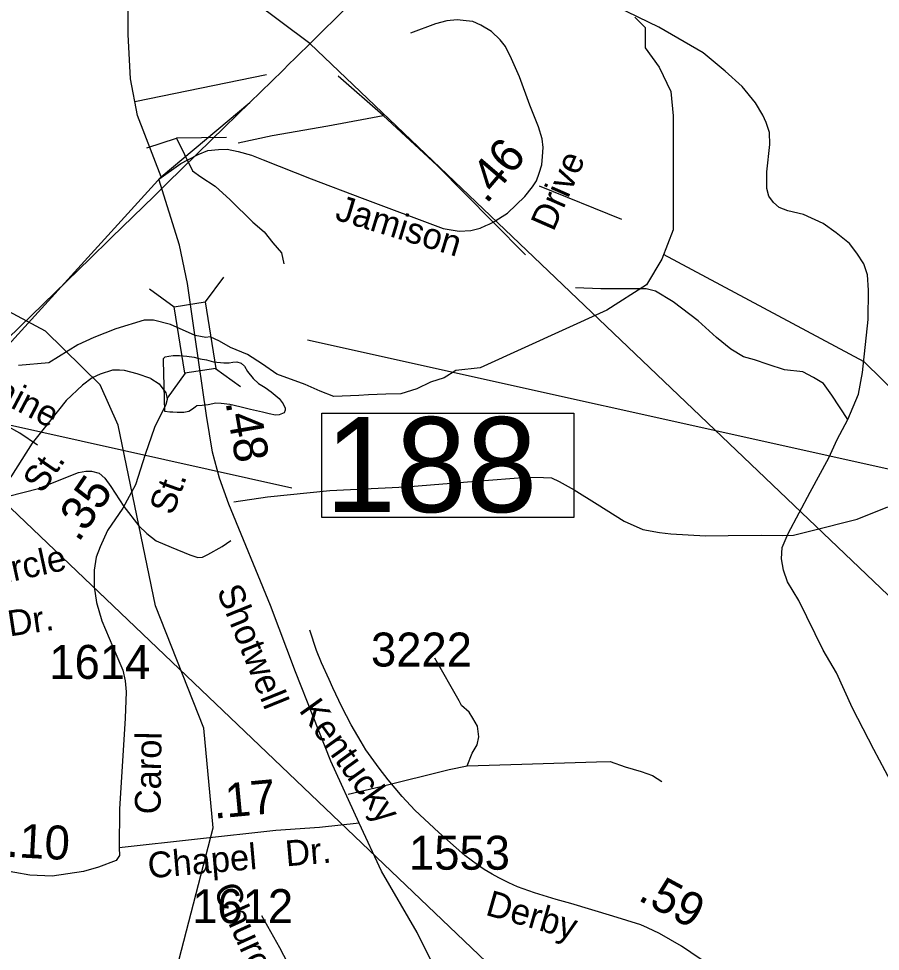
# Model space of a CAD drawing. Extents: x 2169602 to 2449496, y 721995 to 810662.
# Drawn here: x 2397017 to 2400191, y 770629 to 774064 of the extents above; entities that cross this region are included whole.
import ezdxf

# ---------------------------------------------------------------- set-up
doc = ezdxf.new("R2010")
doc.units = 0
doc.layers.add('Default', color=7, linetype='Continuous')

msp = doc.modelspace()

# ---------------------------------------------------------------- linework, layer by layer
at = {"layer": 'Default'}
for p, q in [((2397929.8, 773856.9), (2397444.7, 773758.4)), ((2398359.1, 773708), (2398194.2, 773852.1)), ((2397488.4, 773587.9), (2397598.6, 773623.5)), ((2397782.5, 773626.3), (2397598.6, 773623.5)), ((2397598.6, 773623.5), (2397657.5, 773503.9)), ((2398934, 773448.1), (2399237.7, 773326.2)), ((2398764.9, 773314.7), (2398884.4, 773194.6)), ((2397770.8, 773112.6), (2397704.2, 773021)), ((2397498.3, 773069.4), (2397589.9, 773002.9)), ((2395064.8, 772994), (2398022.8, 772336.6)), ((2398080.6, 772881.1), (2401038.6, 772223.8)), ((2397742.5, 772776.1), (2397834.1, 772709.6)), ((2397630.7, 772758.4), (2397564.2, 772666.8))]:
    msp.add_line(p, q, dxfattribs=at)
for points in [[(2389396, 765530.5), (2389873.7, 765993.4), (2389932.2, 766050), (2389976.3, 766092.7), (2391349.7, 767422.8), (2391498.4, 767552.8), (2391855.4, 767888.1), (2392186.8, 768223.2), (2394046.1, 769967.9), (2396780.6, 772645.2), (2397542.2, 773482.1), (2397868.3, 773755.4), (2397989.5, 773873.8), (2398013.9, 773897.7), (2398034.4, 773917.9), (2398098.8, 773981.2), (2398223.7, 774104.3), (2398525.7, 774401.5), (2398527.8, 774403.5), (2398862.2, 774727.1), (2399383.8, 775209.8), (2399485.8, 775316.7)], [(2398089.9, 773972.5), (2397778.5, 774206.3), (2397521.3, 774474.8)], [(2397542.2, 773482.1), (2397454.6, 773707.2), (2397428.5, 773842.2), (2397420.6, 774005.6), (2397420.6, 774129.1), (2397425.9, 774209.8), (2397445.2, 774303)], [(2400071.9, 772588.2), (2400110.4, 772680.5), (2400125.8, 772760.9), (2400146.3, 772955.9), (2400147.2, 773063.7), (2400143.7, 773120.1), (2400130, 773161.2), (2400104.4, 773200.5), (2400077.9, 773236.5), (2400028.3, 773275.8), (2399980.4, 773310), (2399908.5, 773342.5), (2399850.4, 773356.2), (2399817.9, 773368.2), (2399797.4, 773387), (2399780.3, 773410.9), (2399773.4, 773438.3), (2399773.4, 773499.9), (2399784.5, 773600.8), (2399782.8, 773645.3), (2399770.8, 773681.2), (2399758.9, 773708.6), (2399731.5, 773754.7), (2399681.9, 773814.6), (2399619.5, 773871), (2399539.1, 773937.8), (2399374.9, 774033.5), (2399103.8, 774165.3)], [(2392186.8, 768223.2), (2394046.1, 769967.9), (2396780.6, 772645.2), (2397542.2, 773482.1), (2397868.3, 773755.4), (2397989.5, 773873.8), (2398013.9, 773897.7), (2398034.4, 773917.9), (2398098.8, 773981.2), (2398223.7, 774104.3)], [(2410998.9, 759007.9), (2409859, 760053.1), (2407211.5, 762601.4), (2405778.5, 763946.8), (2405684, 764042.1), (2405083.2, 764574.5), (2404665, 764982.2), (2402074.2, 767418.4), (2399573.8, 769793.5), (2395074.1, 774085.3)], [(2396844.7, 772758.7), (2397281, 773182), (2397351.2, 773250.5), (2397359, 773258.1), (2397515.4, 773410.9), (2397538.8, 773433.8), (2397562.2, 773456.7), (2397563.4, 773457.8), (2397727.6, 773618.2), (2397868.3, 773755.4), (2397989.5, 773873.8), (2398013.9, 773897.8), (2398034.4, 773918), (2398098.8, 773981.2), (2398223.7, 774104.3)], [(2399287.2, 774069.4), (2399324.9, 774031.7), (2399324.9, 773956.3), (2399376.7, 773885.6), (2399419.1, 773796), (2399428.5, 773706.4), (2399428.5, 773451.9), (2399428.5, 773286.9), (2399386.1, 773178.5), (2399329.6, 773084.2), (2399183.6, 772989.9), (2398717.2, 772777.8), (2398627.7, 772768.4), (2398584.3, 772741.1), (2398534.3, 772725.6), (2398483.5, 772700.6), (2398424.9, 772682.5), (2398369.7, 772681.6), (2398305.1, 772678.2), (2398269.7, 772675.6), (2398178, 772672.9), (2398128.1, 772691.5), (2398072.5, 772717.1), (2397968.3, 772754.2), (2397915.3, 772791.5), (2397859.2, 772827.6), (2397796.9, 772852.5), (2397757.1, 772876.2), (2397722.2, 772892.4), (2397706, 772889.9), (2397667.2, 772897.4), (2397576, 772938), (2397514, 772953.3), (2397479.1, 772953.4), (2397374.5, 772921.4), (2397293.1, 772889.4), (2397234.9, 772863.2), (2397127.4, 772796.3), (2397016.6, 772787.2)], [(2397533.5, 773472.5), (2397614.8, 773530.6), (2397640, 773543.7), (2397678, 773564.2), (2397713.4, 773578.2), (2397753.4, 773581.7), (2397784.5, 773582.9), (2397825, 773574.8), (2397874.8, 773561.1), (2397917.7, 773544.3), (2398094.3, 773474.6), (2398282.6, 773403), (2398580.9, 773291.5), (2398640, 773281.5), (2398682.4, 773283.4), (2398716.6, 773292.1), (2398737.9, 773302.8), (2398749.6, 773307.4), (2398764.9, 773314.7), (2398817.9, 773347.3), (2398881, 773408.6), (2398910.3, 773444.7), (2398924, 773467.1), (2398933.9, 773494.5), (2398944.5, 773525.6), (2398947, 773556.1), (2398948.9, 773589.1), (2398945.8, 773621.5), (2398932.1, 773665.7), (2398900, 773746.1), (2398861.4, 773849.4), (2398832.4, 773916), (2398810.7, 773962.1), (2398790.1, 773986.4), (2398759, 774017.5), (2398719.7, 774040), (2398690.5, 774053.7), (2398665, 774056.8), (2398631.9, 774060.5), (2398594.3, 774056.8), (2398551.9, 774045.6), (2398459.8, 774011.3)], [(2414014.7, 758895), (2412874.9, 759940.3), (2410227.4, 762488.5), (2408794.3, 763834), (2408699.9, 763929.3), (2408099, 764461.7), (2407680.9, 764869.3), (2405090.1, 767305.6), (2402589.6, 769680.7), (2398089.9, 773972.5)], [(2397825.5, 773606.6), (2397951, 773634.2), (2398155.4, 773669.6), (2398300.9, 773696.2), (2398359.1, 773708)], [(2398359.1, 773708), (2398558.7, 773523.7), (2398764.9, 773314.7)], [(2397657.5, 773503.9), (2397687.9, 773481.7), (2397740.2, 773447.8), (2397796.4, 773396.3), (2397878.9, 773314.8), (2397920.9, 773279), (2397953.3, 773239.1), (2397985.5, 773201.5), (2397993.7, 773161.5)], [(2397666.2, 772899.8), (2397638.8, 773089.1), (2397608.9, 773229.9), (2397533.5, 773472.5)], [(2398080.6, 767097), (2398111.6, 767572), (2398093.6, 767736.3), (2398174.8, 768180.8), (2398115.7, 768313.2), (2397956.6, 768460.8), (2397578.7, 768983.5), (2397502.6, 769142.5), (2397468.8, 769307.2), (2397483.8, 769592.3), (2397524.8, 769768.7), (2397562.7, 770424), (2397733.8, 771083.1), (2397698.7, 771451.2), (2397520.7, 771900.9), (2397383.8, 772566.4), (2397316.9, 772715.3), (2397115.8, 772913), (2396376.9, 773308.2)], [(2401096.5, 766984.1), (2401127.4, 767459.1), (2401109.4, 767623.5), (2401190.6, 768068), (2401131.6, 768200.3), (2400972.4, 768348), (2400594.5, 768870.7), (2400518.5, 769029.7), (2400484.6, 769194.4), (2400499.6, 769479.5), (2400540.6, 769655.8), (2400578.6, 770311.1), (2400749.6, 770970.3), (2400714.5, 771338.4), (2400536.5, 771788.1), (2400399.6, 772453.5), (2400332.7, 772602.5), (2400131.6, 772800.1), (2399392.8, 773195.4)], [(2400071.9, 772588.2), (2400012, 772677.1), (2399981.2, 772719.9), (2399945.3, 772742.1), (2399906, 772762.7), (2399837.6, 772771.2), (2399777.7, 772790), (2399728.1, 772807.1), (2399687, 772819.1), (2399640.8, 772846.5), (2399587.8, 772889.2), (2399520.3, 772950.8), (2399427.9, 773020.9), (2399362.9, 773060.3), (2399328.7, 773068.8), (2399285.9, 773068.8), (2399161.1, 773068.8), (2399068.7, 773072.2)], [(2398271.4, 771100.3), (2398166.2, 771329.5), (2398036.7, 771658.2), (2397944.5, 771902.3), (2397791.3, 772275.9), (2397756.5, 772371.8), (2397730.3, 772467.7), (2397708.5, 772602.2), (2397666.2, 772899.8)], [(2397555.2, 772617), (2397550.5, 772805.1), (2397550.5, 772812.8), (2397556.2, 772818.9), (2397570.2, 772821.2), (2397585.7, 772823.3), (2397609.9, 772823.3), (2397636, 772821.4), (2397663.9, 772817.6), (2397685.8, 772811.8), (2397708.6, 772807.9), (2397734, 772800), (2397772.5, 772796.2), (2397792, 772796.1), (2397806, 772798.5), (2397820.3, 772800.4), (2397836.5, 772794.7), (2397848.4, 772784.8), (2397860.3, 772764.7), (2397880.6, 772738.9), (2397900.7, 772720.9), (2397924.7, 772705.1), (2397946.8, 772689.2), (2397976.8, 772665.6), (2397990.9, 772645.6), (2397998.9, 772629.4), (2397998.9, 772621.7), (2397995, 772611.7), (2397977, 772605.5), (2397963, 772603.5), (2397939.5, 772609.2), (2397915.3, 772614.9), (2397871, 772624.8), (2397831, 772634.5), (2397794.9, 772642.4), (2397763.3, 772646.4), (2397743.2, 772648.2), (2397714.9, 772641.9), (2397693, 772639.9), (2397673.1, 772637.7), (2397667.1, 772633.7), (2397657.3, 772625.4), (2397643.4, 772617.4), (2397625.1, 772613.3), (2397601.3, 772613.2), (2397585.1, 772615.3), (2397573.2, 772615.1), (2397555.2, 772617)], [(2397503.7, 772738.3), (2397453.4, 772755.6), (2397406.5, 772768.2), (2397388.3, 772769.7), (2397362.8, 772769.4), (2397317.4, 772754.7), (2397288.1, 772741.1), (2397252, 772713.7), (2397192.2, 772657.6), (2397129.9, 772580.4), (2397067, 772500.1), (2396990.8, 772380.5), (2396931.6, 772300.8), (2396899.2, 772235.4), (2396876.8, 772172.6), (2396851.3, 772083.5), (2396796.2, 771892.4), (2396664.2, 771359.3), (2396601.3, 771118.4), (2396594.4, 771049.9), (2396600, 771032.4), (2396621.8, 771015.6), (2396671, 771000.1), (2396894.1, 770944.8)], [(2397503.7, 772738.3), (2397534.3, 772718.6), (2397558.6, 772686.3), (2397561.1, 772675.7), (2397564.2, 772662), (2397559.3, 772643.3), (2397516.7, 772558.6), (2397483.1, 772458.4), (2397446.7, 772346.9), (2397400.6, 772261), (2397344.6, 772178.8), (2397317.5, 772118.4), (2397302.5, 772081), (2397294.5, 772032.5), (2397294.5, 771971.4), (2397303.8, 771913.5), (2397323.4, 771846.3), (2397363.3, 771750.4), (2397400.6, 771664.5), (2397409.3, 771624.6), (2397412.4, 771584.1), (2397409.3, 771487), (2397388.8, 771152.6), (2397386.9, 771010)], [(2397086.5, 772493.1), (2397021.3, 772536.8), (2396913.9, 772596.5), (2396862.2, 772627), (2396830.4, 772638.9), (2396807.7, 772644.9), (2396780.6, 772645.2)], [(2400504.6, 770797.3), (2400447.3, 770898.2), (2400363.5, 771031.6), (2400230.1, 771254), (2400167.7, 771372), (2400089, 771524.3), (2400030, 771654.3), (2399980.4, 771738.1), (2399891.4, 771921.1), (2399849.5, 771989.5), (2399834.1, 772032.3), (2399827.3, 772075), (2399829, 772116.1), (2399851.2, 772167.4), (2399932.5, 772319.6), (2400000.9, 772446.2), (2400031.7, 772514.6), (2400071.9, 772588.2)], [(2396919.8, 772290.4), (2397090.1, 772334), (2397202.6, 772378.8), (2397237.6, 772393), (2397263.8, 772397.4), (2397285.6, 772397.4), (2397312.9, 772389.7), (2397333.7, 772371.2), (2397356.6, 772340.6), (2397404.7, 772267.4), (2397459.3, 772195.9), (2397488.7, 772167.5), (2397523.7, 772141.3), (2397578.3, 772117.3), (2397647.1, 772088.9), (2397676.6, 772079.1), (2397694, 772080.2), (2397713.7, 772090), (2397766.1, 772119.5), (2397798.9, 772141.9)], [(2397809.5, 772284), (2397932.9, 772302.6), (2398163.3, 772326.6), (2398442.8, 772339.2), (2398701.6, 772360.4), (2398888.4, 772375.7), (2398950.6, 772374.1), (2398980.1, 772373), (2399008.5, 772359.9), (2399063.1, 772328.2), (2399148.3, 772275.8), (2399247.6, 772213), (2399316.4, 772182.4), (2399377.6, 772171.5), (2399419.1, 772166.1), (2399546.9, 772159), (2399630.9, 772160.1), (2399754.3, 772161.2), (2399829.7, 772160.1), (2399871.2, 772162.2), (2399935.6, 772177.5), (2400106, 772221.2), (2400218.5, 772266)], [(2399565.9, 770574.9), (2399458.1, 770647.3), (2399377.9, 770694.7), (2399333.5, 770715.7), (2399308.3, 770726.1), (2399205.3, 770758.4), (2399050.5, 770805.1), (2398996.4, 770819.4), (2398917.6, 770843.7), (2398854.1, 770866.8), (2398822, 770881.6), (2398786.3, 770899.6), (2398760.7, 770912.7), (2398731.6, 770930.4), (2398706.6, 770947.4), (2398660.2, 770981.6), (2398565.2, 771066), (2398475.8, 771149.1), (2398429, 771198.8), (2398378, 771260.9), (2398344.4, 771302.9), (2398295.2, 771370.6), (2398278.3, 771400.4), (2398242.3, 771462.5), (2398207.7, 771528.8), (2398174.6, 771599.4), (2398160.2, 771629.9), (2398132.6, 771691.7), (2398114.2, 771737.4), (2398089.5, 771811.4)], [(2398669.2, 771311.5), (2398687.4, 771358.5), (2398706, 771389.1), (2398712.6, 771418.6), (2398707.1, 771457.9), (2398689.6, 771487.4), (2398676.5, 771510.3), (2398648.1, 771534.3), (2398639.4, 771551.8), (2398549.8, 771709.1)], [(2398669.2, 771311.5), (2398870.9, 771318.7), (2399146.1, 771326.3), (2399196.3, 771328.5), (2399250.9, 771308.8), (2399309.9, 771291.4), (2399351.4, 771276.1), (2399386.3, 771254.2)], [(2398231, 771207.3), (2398351.1, 771235.7), (2398602.3, 771299), (2398669.2, 771311.5)], [(2398271.4, 771100.3), (2398124.5, 771084.5), (2397964.3, 771073.6), (2397386.9, 771010)], [(2398911.9, 769030.3), (2398908.7, 769229.4), (2398903.3, 769505.5), (2398896.9, 769718.5), (2398890.5, 769788), (2398898.2, 769852.6), (2398875.3, 769911.6), (2398830.5, 770023), (2398775.9, 770124.5), (2398713.7, 770268.1), (2398582.6, 770499.6), (2398484.3, 770698.4), (2398353.6, 770923.5), (2398271.4, 771100.3)], [(2397386.9, 771010), (2397388.2, 770981.4), (2397376.3, 770962.7), (2397310.3, 770938.4), (2397255.5, 770922.9), (2397140.5, 770905.4), (2397058.3, 770909.8), (2396945.6, 770928.5), (2396894.1, 770944.8)], [(2398039.1, 770526), (2397978.4, 770641.4), (2397912, 770759.8)]]:
    msp.add_lwpolyline(points, dxfattribs=at)
for points in [[(2397704.2, 773021), (2397743, 772776.2), (2397628.7, 772758.1), (2397589.9, 773002.9)], [(2398133.5, 772610.8), (2399062.5, 772610.8), (2399062.5, 772226.7), (2398133.5, 772226.7)]]:
    msp.add_lwpolyline(points, close=True, dxfattribs=at)

# ---------------------------------------------------------------- texts
for s, height, rotation, p in [('.46', 125, 49.4379, (2398739.8, 773378.8)), ('Drive', 95, 66.3904, (2398986.9, 773277)), ('Jamison', 95, 343.0006, (2398178.1, 773325.1)), ('Elaine', 95, 332.2311, (2396821, 772718.5)), ('.48', 125, 279.6888, (2397778.4, 772651.7)), ('St.', 95, 55.3623, (2397103.7, 772311.7)), ('.35', 125, 55.7131, (2397237.1, 772132.1)), ('St.', 95, 70.1417, (2397584.8, 772231.6)), ('Circle', 95, 12.3387, (2396881.5, 771965.8)), ('Shotwell', 95, 292.1209, (2397745, 771957.3)), ('Dr.', 95, 8.512, (2396983.6, 771788.4)), ('Kentucky', 95, 305.6543, (2398046.8, 771516.4)), ('Carol', 95, 89.2657, (2397539.4, 771133)), ('.17', 125, 5.3745, (2397737.3, 771117.1)), ('.10', 125, 356.9644, (2396970.1, 770977)), ('Chapel   Dr.', 95, 4.9729, (2397496.2, 770897.4)), ('.59', 125, 331.5918, (2399294, 770819.8)), ('Churchill', 95, 294.2828, (2397732.4, 770855.7)), ('Derby', 95, 343.9183, (2398732.6, 770763.9))]:
    msp.add_text(s, height=height, rotation=rotation, dxfattribs=at).set_placement(p)
for s, height, p in [('188', 350, (2398146, 772246.5)), ('3222', 125, (2398314.8, 771677.9)), ('1614', 125, (2397129.8, 771632.3)), ('1553', 125, (2398454.8, 770929.4)), ('1612', 125, (2397656, 770732.7))]:
    msp.add_text(s, height=height, dxfattribs=at).set_placement(p)

doc.saveas('drawing.dxf')
